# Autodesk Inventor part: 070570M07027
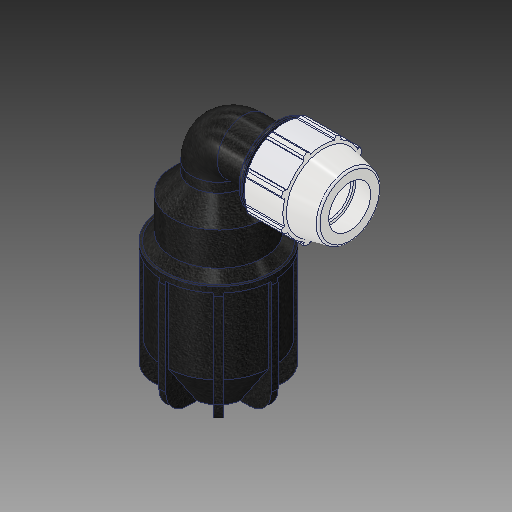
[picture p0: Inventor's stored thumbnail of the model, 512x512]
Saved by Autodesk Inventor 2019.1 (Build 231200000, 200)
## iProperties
Created: 2017-02
Part Number: 070570M07027
Material: PVC-Piping
Description: PLASSON PLASS4 90° ELBOW 3/4'' - 0.925
Document SubType Name: Modeling
Designer: KIM
Mass: 92.6774 g
Surface Area: 199.44 cm^2
Volume: 66.1981 cm^3
Density: 1.4 g/cm^3
Appearance: PTFE
Author: KIM
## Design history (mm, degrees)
derived "070570M0.ipt"
feature "Solid1::070570M0.ipt"
tag "TaggingFeature1"
body "Solid1"
other parameters: "d2" = 26.6, "d4" = 11.86543, "d5" = 16.6116, "d7" = 54.102, "d8" = 33.99789, "d9" = 11.86543, "d11" = 2.37309, "d12" = 43.2816, "d13" = 120 deg, "d14" = 39.9, "d15" = 12 deg, "d16" = 48.6918, "d18" = 1.33, "d19" = 35 deg, "d20" = 17.5 deg, "d21" = 50.31486, "d23" = 0, "d25" = 360 deg, "d27" = 1.08204, "d42" = 24.9174, "d43" = 1.62306, "d46" = 0.798, "d53" = 0.532, "d67" = 2.7051, "d70" = 23.94, "d71" = 59.944, "d73" = 83.058, "d74" = 90 deg, "d75" = 23.495, "d76" = 71.12, "d77" = 138.938, "d78" = 0.83058, "d80" = 23.94, "d82" = 104.902, "d84" = 67.564, "d85" = 135 deg, "d86" = 3.556, "d88" = 104.902, "d89" = 3.556, "d90" = 135 deg, "d91" = 78.6765, "d92" = 22.23008, "d93" = 26.2255, "d94" = 3.556, "d95" = 5.2451, "d97" = 4.32816, "d98" = 0, "d100" = 360 deg, "d102" = 78.232, "d103" = 14.224, "d104" = 5.6896, "d105" = 0, "d107" = 16.2306, "d108" = 0, "d109" = 0, "d110" = 2.37309, "d_" = 26.6, "E_" = 54.102, "A_" = 83.058, "l_" = 59.944, "d_1" = 23.495, "E_1" = 71.12, "l_1" = 104.902, "A_1" = 138.938, "d106" = 33.99789
